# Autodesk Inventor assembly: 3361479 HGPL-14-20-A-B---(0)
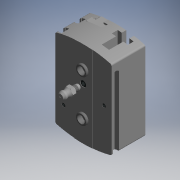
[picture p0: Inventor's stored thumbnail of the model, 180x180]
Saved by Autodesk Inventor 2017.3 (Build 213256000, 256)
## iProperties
Category: PARTsolutions
Company: FESTO
Part Number: 3361479 HGPL-14-20-A-B---(0)
Catalog Web Link: www.cadenas.de
Description: HGPL-B-Parallel gripper
Vendor: FESTO
Document SubType Name: Assembly
Designer: partserver
Manufacturer: FESTO
Mass: 305 g
Surface Area: 358.431 cm^2
Volume: 79.5066 cm^3
Density: 3.83616 g/cm^3
Title: 3361479 HGPL-14-20-A-B---(0)
Author: Cadenas PARTsolutions
Comments: Parallel gripper
PSOL_IDENT_0: {ATYP=ASSISTANT},{DATA=script=$CADENAS_DATA/23d-libs/festo/webfesto.vbb/&M_FAMILY=HGPL&M_GROUP=01&M_
PSOL_IDENT_1: PARTNO=3361479&IDCODE1=HGPL-14-20-A-B&IDCODE2=&customer_number_cns=&MATES=1&LOD=HI&LOCKERP=0&SINGLEP
PSOL_IDENT_2: ART=1}
NB: 3361479 HGPL-14-20-A-B---(0)
NN: HGPL-B
NT: Parallel gripper
NBSYN: $TNR. $TYP.---($HUBST.)
LINA: 3361479 HGPL-14-20-A-B---(0)
CATALOG: Festo
TNR: 3361479
TYP: HGPL-14-20-A-B
KDM: 14
HUB: 20
HUBST: 0
L1: 73.6
L2: 36
L3: 0
L4: 62
L5: 22
L6: 8
H1: 30
H2: 29
H3: 24.4
H4: 10
H5: 12
H6: 11.2
H7: 0
H10: 4
B1: 48
B2: 34.5
B3: 22
B4: 40
G3: M3
T6: 6.5
CNSMASSEXACT: 0.305
SUPPLIER: FESTO
ARTICLENO: 3361479 HGPL-14-20-A-B---(0)
BOMINFO: 3361479 HGPL-14-20-A-B---(0)
CREATOR: CADENAS GmbH
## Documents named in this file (8)
- e:\temp\worker_61\temp\exporttempdir_840_150_Urm0j\format_0\3361479 HGPL-14-20-A-B---(0).iam
- e:\temp\worker_61\temp\exporttempdir_840_150_Urm0j\format_0\3361628 HGPL-14-20-A-B---(GEH).ipt
- e:\temp\worker_61\temp\exporttempdir_840_150_Urm0j\format_0\3361610 HGPL-BAC-14-20---(J).ipt
- e:\temp\worker_61\temp\exporttempdir_840_150_Urm0j\format_0\189652 ZBH-5.ipt
- e:\temp\worker_61\temp\exporttempdir_840_150_Urm0j\format_0\DIN-913 - M3x3.ipt
- e:\temp\worker_61\temp\exporttempdir_840_150_Urm0j\format_0\DIN-913 - M5x5.ipt
- e:\temp\worker_61\temp\exporttempdir_840_150_Urm0j\format_0\DIN-71412 A M5x0_8_SW7.ipt
- e:\temp\worker_61\temp\exporttempdir_840_150_Urm0j\format_0\150927 ZBH-9.ipt
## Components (14 placed, 7 different names)
1. 3361628 HGPL-14-20-A-B---(GEH):1 — JAW1_Z@1 <-> ANBAU_Z@2, JAW1_YZ@1 <-> ANBAU_YZ@2, PIN_1_XY@1 <-> IP1_XY@8, PIN_1_Z@1 <-> IP1_Z@8, PIN_1_YZ@1 <-> IP1_YZ@8, PIN_2_XY@1 <-> IP1_XY@9, PIN_2_Z@1 <-> IP1_Z@9, PIN_2_YZ@1 <-> IP1_YZ@9, NIPPEL_OBEN_XY@1 <-> IP1_XY@10, NIPPEL_OBEN_Z@1 <-> IP1_Z@10, NIPPEL_OBEN_YZ@1 <-> IP1_YZ@10, NIPPEL_UNTEN_XY@1 <-> IP1_XY@11, NIPPEL_UNTEN_Z@1 <-> IP1_Z@11, NIPPEL_UNTEN_YZ@1 <-> IP1_YZ@11, NIPPEL_XY@1 <-> ANBAU_XY@12, NIPPEL_Z@1 <-> ANBAU_Z@12, NIPPEL_YZ@1 <-> ANBAU_YZ@12, ZBH_UNTEN_1_XY@1 <-> insert_XY@13, ZBH_UNTEN_1_Z@1 <-> insert_Z@13, ZBH_UNTEN_1_YZ@1 <-> insert_YZ@13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
2. 3361610 HGPL-BAC-14-20---(J):1 — JAW1_Z@1 <-> ANBAU_Z@2, JAW1_YZ@1 <-> ANBAU_YZ@2, ZBHJAW1_XY@2 <-> insert_XY@3, ZBHJAW1_Z@2 <-> insert_Z@3, ZBHJAW1_YZ@2 <-> insert_YZ@3, ZBHJAW2_XY@2 <-> insert_XY@4, ZBHJAW2_Z@2 <-> insert_Z@4, ZBHJAW2_YZ@2 <-> insert_YZ@4
3. 189652 ZBH-5:1 — ZBHJAW1_XY@2 <-> insert_XY@3, ZBHJAW1_Z@2 <-> insert_Z@3, ZBHJAW1_YZ@2 <-> insert_YZ@3
4. 189652 ZBH-5:2 — ZBHJAW2_XY@2 <-> insert_XY@4, ZBHJAW2_Z@2 <-> insert_Z@4, ZBHJAW2_YZ@2 <-> insert_YZ@4
5. 3361610 HGPL-BAC-14-20---(J):2 — ZBHJAW1_XY@5 <-> insert_XY@6, ZBHJAW1_Z@5 <-> insert_Z@6, ZBHJAW1_YZ@5 <-> insert_YZ@6, ZBHJAW2_XY@5 <-> insert_XY@7, ZBHJAW2_Z@5 <-> insert_Z@7, ZBHJAW2_YZ@5 <-> insert_YZ@7
6. 189652 ZBH-5:3 — ZBHJAW1_XY@5 <-> insert_XY@6, ZBHJAW1_Z@5 <-> insert_Z@6, ZBHJAW1_YZ@5 <-> insert_YZ@6
7. 189652 ZBH-5:4 — ZBHJAW2_XY@5 <-> insert_XY@7, ZBHJAW2_Z@5 <-> insert_Z@7, ZBHJAW2_YZ@5 <-> insert_YZ@7
8. DIN-913 - M3x3:1 — PIN_1_XY@1 <-> IP1_XY@8, PIN_1_Z@1 <-> IP1_Z@8, PIN_1_YZ@1 <-> IP1_YZ@8
9. DIN-913 - M3x3:2 — PIN_2_XY@1 <-> IP1_XY@9, PIN_2_Z@1 <-> IP1_Z@9, PIN_2_YZ@1 <-> IP1_YZ@9
10. DIN-913 - M5x5:1 — NIPPEL_OBEN_XY@1 <-> IP1_XY@10, NIPPEL_OBEN_Z@1 <-> IP1_Z@10, NIPPEL_OBEN_YZ@1 <-> IP1_YZ@10
11. DIN-913 - M5x5:2 — NIPPEL_UNTEN_XY@1 <-> IP1_XY@11, NIPPEL_UNTEN_Z@1 <-> IP1_Z@11, NIPPEL_UNTEN_YZ@1 <-> IP1_YZ@11
12. DIN-71412 A M5x0_8_SW7:1 — NIPPEL_XY@1 <-> ANBAU_XY@12, NIPPEL_Z@1 <-> ANBAU_Z@12, NIPPEL_YZ@1 <-> ANBAU_YZ@12
13. 150927 ZBH-9:1 — ZBH_UNTEN_1_XY@1 <-> insert_XY@13, ZBH_UNTEN_1_Z@1 <-> insert_Z@13, ZBH_UNTEN_1_YZ@1 <-> insert_YZ@13
14. 150927 ZBH-9:2 — ZBH_UNTEN_2_XY@1 <-> insert_XY@14, ZBH_UNTEN_2_Z@1 <-> insert_Z@14, ZBH_UNTEN_2_YZ@1 <-> insert_YZ@14
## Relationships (35: Mate 21, Angle 12, Flush 2)
- JAW1_Z@1 <-> ANBAU_Z@2 [Mate]: 3361628 HGPL-14-20-A-B---(GEH):1 ↔ 3361610 HGPL-BAC-14-20---(J):1
- JAW1_YZ@1 <-> ANBAU_YZ@2 [Angle]: 3361628 HGPL-14-20-A-B---(GEH):1 ↔ 3361610 HGPL-BAC-14-20---(J):1
- ZBHJAW1_XY@2 <-> insert_XY@3 [Mate]: 3361610 HGPL-BAC-14-20---(J):1 ↔ 189652 ZBH-5:1
- ZBHJAW1_Z@2 <-> insert_Z@3 [Mate]: 3361610 HGPL-BAC-14-20---(J):1 ↔ 189652 ZBH-5:1
- ZBHJAW1_YZ@2 <-> insert_YZ@3 [Angle]: 3361610 HGPL-BAC-14-20---(J):1 ↔ 189652 ZBH-5:1
- ZBHJAW2_XY@2 <-> insert_XY@4 [Mate]: 3361610 HGPL-BAC-14-20---(J):1 ↔ 189652 ZBH-5:2
- ZBHJAW2_Z@2 <-> insert_Z@4 [Mate]: 3361610 HGPL-BAC-14-20---(J):1 ↔ 189652 ZBH-5:2
- ZBHJAW2_YZ@2 <-> insert_YZ@4 [Angle]: 3361610 HGPL-BAC-14-20---(J):1 ↔ 189652 ZBH-5:2
- ZBHJAW1_XY@5 <-> insert_XY@6 [Mate]: 3361610 HGPL-BAC-14-20---(J):2 ↔ 189652 ZBH-5:3
- ZBHJAW1_Z@5 <-> insert_Z@6 [Mate]: 3361610 HGPL-BAC-14-20---(J):2 ↔ 189652 ZBH-5:3
- ZBHJAW1_YZ@5 <-> insert_YZ@6 [Angle]: 3361610 HGPL-BAC-14-20---(J):2 ↔ 189652 ZBH-5:3
- ZBHJAW2_XY@5 <-> insert_XY@7 [Mate]: 3361610 HGPL-BAC-14-20---(J):2 ↔ 189652 ZBH-5:4
- ZBHJAW2_Z@5 <-> insert_Z@7 [Mate]: 3361610 HGPL-BAC-14-20---(J):2 ↔ 189652 ZBH-5:4
- ZBHJAW2_YZ@5 <-> insert_YZ@7 [Angle]: 3361610 HGPL-BAC-14-20---(J):2 ↔ 189652 ZBH-5:4
- PIN_1_XY@1 <-> IP1_XY@8 [Mate]: 3361628 HGPL-14-20-A-B---(GEH):1 ↔ DIN-913 - M3x3:1
- PIN_1_Z@1 <-> IP1_Z@8 [Mate]: 3361628 HGPL-14-20-A-B---(GEH):1 ↔ DIN-913 - M3x3:1
- PIN_1_YZ@1 <-> IP1_YZ@8 [Angle]: 3361628 HGPL-14-20-A-B---(GEH):1 ↔ DIN-913 - M3x3:1
- PIN_2_XY@1 <-> IP1_XY@9 [Mate]: 3361628 HGPL-14-20-A-B---(GEH):1 ↔ DIN-913 - M3x3:2
- PIN_2_Z@1 <-> IP1_Z@9 [Mate]: 3361628 HGPL-14-20-A-B---(GEH):1 ↔ DIN-913 - M3x3:2
- PIN_2_YZ@1 <-> IP1_YZ@9 [Angle]: 3361628 HGPL-14-20-A-B---(GEH):1 ↔ DIN-913 - M3x3:2
- NIPPEL_OBEN_XY@1 <-> IP1_XY@10 [Flush]: 3361628 HGPL-14-20-A-B---(GEH):1 ↔ DIN-913 - M5x5:1
- NIPPEL_OBEN_Z@1 <-> IP1_Z@10 [Mate]: 3361628 HGPL-14-20-A-B---(GEH):1 ↔ DIN-913 - M5x5:1
- NIPPEL_OBEN_YZ@1 <-> IP1_YZ@10 [Angle]: 3361628 HGPL-14-20-A-B---(GEH):1 ↔ DIN-913 - M5x5:1
- NIPPEL_UNTEN_XY@1 <-> IP1_XY@11 [Flush]: 3361628 HGPL-14-20-A-B---(GEH):1 ↔ DIN-913 - M5x5:2
- NIPPEL_UNTEN_Z@1 <-> IP1_Z@11 [Mate]: 3361628 HGPL-14-20-A-B---(GEH):1 ↔ DIN-913 - M5x5:2
- NIPPEL_UNTEN_YZ@1 <-> IP1_YZ@11 [Angle]: 3361628 HGPL-14-20-A-B---(GEH):1 ↔ DIN-913 - M5x5:2
- NIPPEL_XY@1 <-> ANBAU_XY@12 [Mate]: 3361628 HGPL-14-20-A-B---(GEH):1 ↔ DIN-71412 A M5x0_8_SW7:1
- NIPPEL_Z@1 <-> ANBAU_Z@12 [Mate]: 3361628 HGPL-14-20-A-B---(GEH):1 ↔ DIN-71412 A M5x0_8_SW7:1
- NIPPEL_YZ@1 <-> ANBAU_YZ@12 [Angle]: 3361628 HGPL-14-20-A-B---(GEH):1 ↔ DIN-71412 A M5x0_8_SW7:1
- ZBH_UNTEN_1_XY@1 <-> insert_XY@13 [Mate]: 3361628 HGPL-14-20-A-B---(GEH):1 ↔ 150927 ZBH-9:1
- ZBH_UNTEN_1_Z@1 <-> insert_Z@13 [Mate]: 3361628 HGPL-14-20-A-B---(GEH):1 ↔ 150927 ZBH-9:1
- ZBH_UNTEN_1_YZ@1 <-> insert_YZ@13 [Angle]: 3361628 HGPL-14-20-A-B---(GEH):1 ↔ 150927 ZBH-9:1
- ZBH_UNTEN_2_XY@1 <-> insert_XY@14 [Mate]: 3361628 HGPL-14-20-A-B---(GEH):1 ↔ 150927 ZBH-9:2
- ZBH_UNTEN_2_Z@1 <-> insert_Z@14 [Mate]: 3361628 HGPL-14-20-A-B---(GEH):1 ↔ 150927 ZBH-9:2
- ZBH_UNTEN_2_YZ@1 <-> insert_YZ@14 [Angle]: 3361628 HGPL-14-20-A-B---(GEH):1 ↔ 150927 ZBH-9:2
